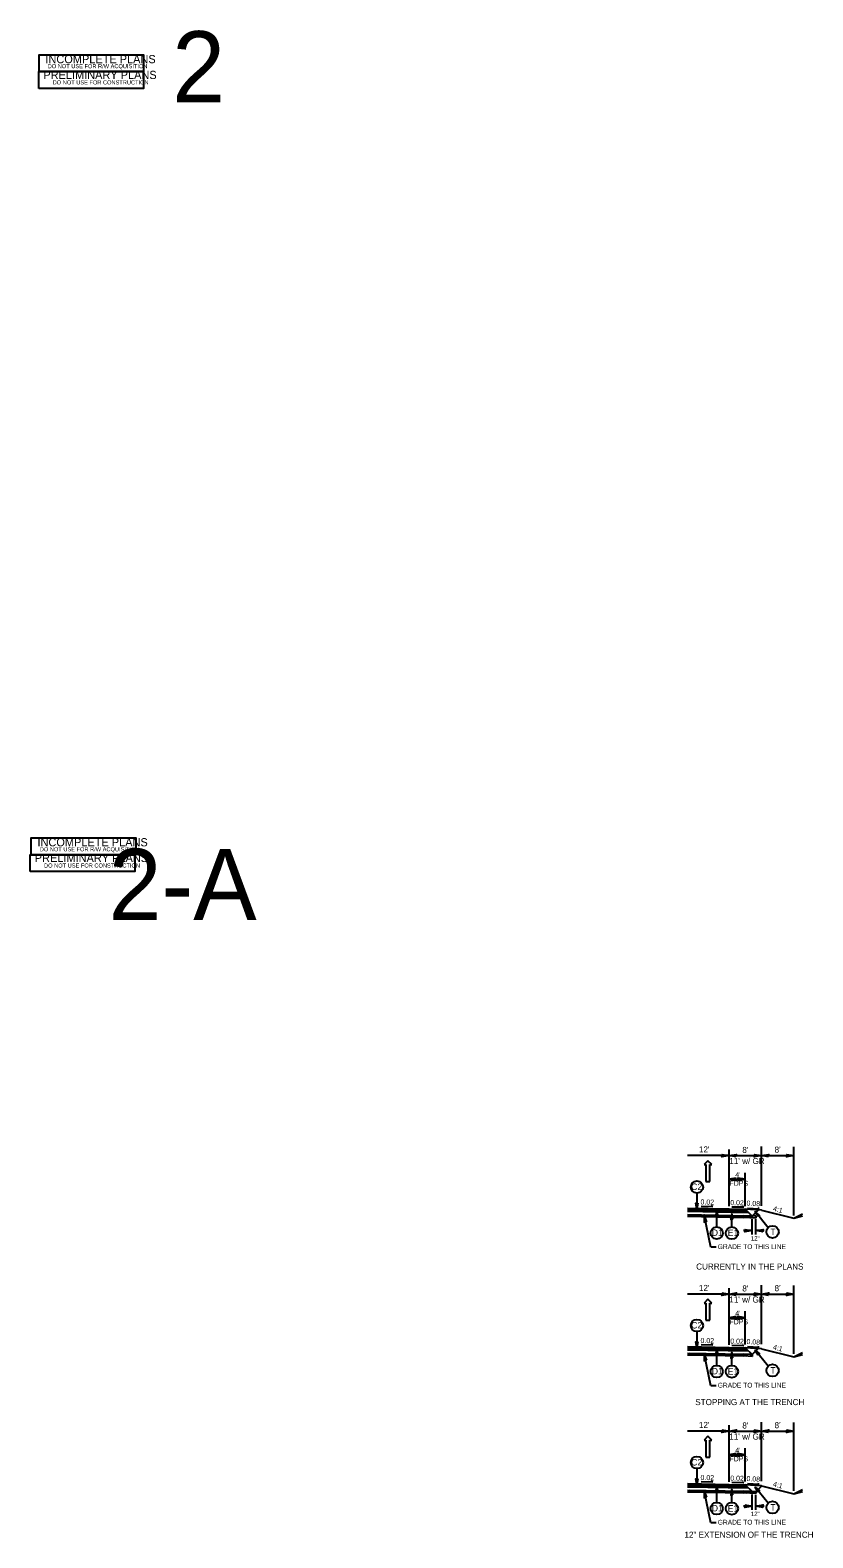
# Model space of a CAD drawing. Extents: x 573813 to 575363, y -54752 to -53123.
# Drawn here: x 575011.9 to 575232, y -53556.2 to -53132.5 of the extents above; entities that cross this region are included whole.
import ezdxf

# ---------------------------------------------------------------- set-up
doc = ezdxf.new("R2010")
doc.units = 0
for name, color, linetype in [('Old_Level_1', 7, 'Continuous'), ('Old_Level_11', 7, 'Continuous'), ('Old_Level_2', 7, 'Continuous'), ('Old_Level_3', 7, 'Continuous'), ('Prop Lane Arrow CELL', 7, 'Continuous'), ('Prop Pavement Schedule Description CELL', 7, 'Continuous'), ('Sheet Data Field CELL', 7, 'Continuous'), ('Sheet Sticker Incomplete CELL', 7, 'Continuous'), ('Sheet Sticker Preliminary CELL', 7, 'Continuous'), ('Typical ID Circle CELL', 7, 'Continuous'), ('Typical Terminator CELL', 7, 'Continuous'), ('Typical Text ID Circle CELL', 7, 'Continuous')]:
    doc.layers.add(name, color=color, linetype=linetype)

msp = doc.modelspace()

# ---------------------------------------------------------------- linework, layer by layer
at = {"layer": 'Old_Level_1'}
for p, q in [((575196.75, -53463.55), (575208.4, -53463.79)), ((575196.75, -53463.99), (575213.4, -53464.34)), ((575196.75, -53464.43), (575213.85, -53464.79)), ((575196.75, -53465.37), (575212.53, -53465.69)), ((575197.03, -53465.37), (575197.54, -53465.88)), ((575198.48, -53465.4), (575198.99, -53465.91)), ((575199.92, -53465.43), (575200.43, -53465.94)), ((575200.54, -53463.01), (575203.8, -53463.08)), ((575201.37, -53465.46), (575201.88, -53465.97)), ((575202.81, -53465.49), (575203.32, -53466)), ((575203.8, -53463.08), (575203.42, -53462.89)), ((575208.4, -53463.79), (575212.95, -53463.88)), ((575212.95, -53463.88), (575214.88, -53465.82)), ((575217.5, -53464.15), (575212.95, -53463.88)), ((575216.6, -53464.1), (575214.88, -53465.82)), ((575217.5, -53464.15), (575226.59, -53466.42)), ((575226.59, -53466.42), (575229.08, -53465.18)), ((575196.75, -53465.87), (575212.52, -53466.19)), ((575204.26, -53465.52), (575204.77, -53466.03)), ((575205.7, -53465.55), (575206.21, -53466.06)), ((575207.14, -53465.58), (575207.65, -53466.09)), ((575208.59, -53465.61), (575209.1, -53466.12)), ((575210.03, -53465.64), (575210.54, -53466.15)), ((575211.48, -53465.67), (575211.99, -53466.18)), ((575215.96, -53466.37), (575212.52, -53466.19)), ((575215.96, -53465.87), (575212.53, -53465.69)), ((575212.93, -53465.71), (575213.46, -53466.24)), ((575214.43, -53465.79), (575214.95, -53466.32)), ((575215.92, -53465.87), (575215.96, -53465.91)), ((575215.96, -53465.87), (575215.96, -53466.37)), ((575226.59, -53466.42), (575229.08, -53465.76)), ((575196.75, -53502.48), (575208.4, -53502.72)), ((575196.75, -53502.92), (575213.4, -53503.27)), ((575196.75, -53503.36), (575213.85, -53503.72)), ((575200.54, -53501.94), (575203.8, -53502.01)), ((575203.8, -53502.01), (575203.42, -53501.82)), ((575208.4, -53502.72), (575212.95, -53502.81)), ((575212.95, -53502.81), (575214.88, -53504.75)), ((575217.5, -53503.08), (575212.95, -53502.81)), ((575216.57, -53503.06), (575214.88, -53504.75)), ((575217.5, -53503.08), (575226.59, -53505.35)), ((575196.75, -53504.3), (575212.53, -53504.63)), ((575196.75, -53504.8), (575212.52, -53505.12)), ((575197.03, -53504.3), (575197.54, -53504.81)), ((575198.48, -53504.33), (575198.99, -53504.84)), ((575199.92, -53504.36), (575200.43, -53504.87)), ((575201.37, -53504.39), (575201.88, -53504.9)), ((575202.81, -53504.42), (575203.32, -53504.93)), ((575204.26, -53504.45), (575204.77, -53504.96)), ((575205.7, -53504.48), (575206.21, -53504.99)), ((575207.14, -53504.51), (575207.65, -53505.02)), ((575208.59, -53504.54), (575209.1, -53505.05)), ((575210.03, -53504.57), (575210.54, -53505.08)), ((575211.48, -53504.6), (575211.99, -53505.11)), ((575214.88, -53505.25), (575212.52, -53505.12)), ((575214.88, -53504.75), (575212.53, -53504.63)), ((575212.93, -53504.65), (575213.46, -53505.17)), ((575214.43, -53504.72), (575214.88, -53505.18)), ((575214.88, -53504.75), (575214.88, -53505.25)), ((575226.59, -53505.35), (575229.08, -53504.11)), ((575226.59, -53505.35), (575229.08, -53504.69)), ((575196.75, -53540.99), (575208.4, -53541.23)), ((575196.75, -53541.44), (575213.4, -53541.78)), ((575200.54, -53540.45), (575203.8, -53540.52)), ((575203.8, -53540.52), (575203.42, -53540.33)), ((575208.4, -53541.23), (575212.95, -53541.33)), ((575212.95, -53541.33), (575214.88, -53543.26)), ((575217.5, -53541.59), (575212.95, -53541.33)), ((575217.64, -53541.63), (575215.96, -53543.32)), ((575217.5, -53541.59), (575226.59, -53543.87)), ((575196.75, -53541.88), (575213.85, -53542.23)), ((575196.75, -53542.81), (575212.53, -53543.14)), ((575196.75, -53543.31), (575212.52, -53543.64)), ((575197.03, -53542.82), (575197.54, -53543.33)), ((575198.48, -53542.85), (575198.99, -53543.36)), ((575199.92, -53542.88), (575200.43, -53543.39)), ((575201.37, -53542.91), (575201.88, -53543.42)), ((575202.81, -53542.94), (575203.32, -53543.45)), ((575204.26, -53542.97), (575204.77, -53543.48)), ((575205.7, -53543), (575206.21, -53543.51)), ((575207.14, -53543.03), (575207.65, -53543.54)), ((575208.59, -53543.06), (575209.1, -53543.57)), ((575210.03, -53543.09), (575210.54, -53543.6)), ((575211.48, -53543.12), (575211.99, -53543.63)), ((575215.96, -53543.82), (575212.52, -53543.64)), ((575215.96, -53543.32), (575212.53, -53543.14)), ((575212.93, -53543.16), (575213.46, -53543.69)), ((575214.43, -53543.24), (575214.95, -53543.76)), ((575215.92, -53543.31), (575215.96, -53543.36)), ((575215.96, -53543.32), (575215.96, -53543.82)), ((575226.59, -53543.87), (575229.08, -53542.62)), ((575226.59, -53543.87), (575229.08, -53543.2))]:
    msp.add_line(p, q, dxfattribs=at)
at = {"layer": 'Old_Level_11'}
for p, q in [((575208.4, -53463.06), (575208.4, -53447.09)), ((575217.5, -53462.9), (575217.5, -53446.29)), ((575226.61, -53465.62), (575226.61, -53446.38)), ((575208.4, -53448.82), (575196.75, -53448.82)), ((575208.4, -53448.82), (575217.5, -53448.82)), ((575217.5, -53448.82), (575226.59, -53448.82)), ((575208.4, -53455.46), (575212.95, -53455.47)), ((575212.95, -53463), (575212.95, -53453.62)), ((575203.29, -53474.58), (575201.38, -53465.46)), ((575214.87, -53470.97), (575214.87, -53466.66)), ((575215.95, -53470.97), (575215.95, -53466.68)), ((575214.87, -53469.89), (575212.44, -53469.9)), ((575218.3, -53469.89), (575215.95, -53469.89)), ((575204.8, -53474.58), (575203.29, -53474.58)), ((575208.4, -53501.99), (575208.4, -53486.02)), ((575217.5, -53501.83), (575217.5, -53485.23)), ((575226.61, -53504.55), (575226.61, -53485.31)), ((575208.4, -53487.75), (575196.75, -53487.75)), ((575208.4, -53487.75), (575217.5, -53487.75)), ((575217.5, -53487.75), (575226.59, -53487.75)), ((575208.4, -53494.39), (575212.95, -53494.4)), ((575212.95, -53501.93), (575212.95, -53492.55)), ((575203.29, -53513.51), (575201.38, -53504.39)), ((575204.8, -53513.51), (575203.29, -53513.51)), ((575208.4, -53540.5), (575208.4, -53524.53)), ((575217.5, -53540.34), (575217.5, -53523.74)), ((575226.61, -53543.06), (575226.61, -53523.82)), ((575208.4, -53526.27), (575196.75, -53526.27)), ((575208.4, -53526.27), (575217.5, -53526.27)), ((575217.5, -53526.27), (575226.59, -53526.27)), ((575208.4, -53532.91), (575212.95, -53532.91)), ((575212.95, -53540.44), (575212.95, -53531.06)), ((575203.29, -53552.02), (575201.38, -53542.91)), ((575214.87, -53548.42), (575214.87, -53544.1)), ((575215.95, -53548.42), (575215.95, -53544.13)), ((575214.87, -53547.34), (575212.44, -53547.34)), ((575218.3, -53547.33), (575215.95, -53547.34)), ((575204.8, -53552.02), (575203.29, -53552.02))]:
    msp.add_line(p, q, dxfattribs=at)
for points in [[(575206.35, -53448.47), (575208.4, -53448.82), (575206.34, -53449.19), (575206.6, -53448.82)], [(575210.45, -53449.17), (575208.4, -53448.82), (575210.46, -53448.46), (575210.2, -53448.82)], [(575215.45, -53448.47), (575217.5, -53448.82), (575215.44, -53449.19), (575215.7, -53448.82)], [(575219.54, -53449.17), (575217.5, -53448.82), (575219.55, -53448.46), (575219.29, -53448.82)], [(575224.55, -53448.47), (575226.59, -53448.82), (575224.54, -53449.19), (575224.8, -53448.82)], [(575210.45, -53455.11), (575208.4, -53455.46), (575210.46, -53455.82), (575210.2, -53455.46)], [(575210.9, -53455.82), (575212.95, -53455.47), (575210.89, -53455.1), (575211.15, -53455.47)], [(575202.15, -53467.39), (575201.38, -53465.46), (575201.45, -53467.55), (575201.75, -53467.22)], [(575212.82, -53469.54), (575214.87, -53469.89), (575212.81, -53470.26), (575213.07, -53469.89)], [(575217.99, -53470.24), (575215.95, -53469.89), (575218, -53469.53), (575217.74, -53469.89)], [(575206.35, -53487.4), (575208.4, -53487.75), (575206.34, -53488.12), (575206.6, -53487.75)], [(575210.45, -53488.11), (575208.4, -53487.75), (575210.46, -53487.39), (575210.2, -53487.75)], [(575215.45, -53487.4), (575217.5, -53487.75), (575215.44, -53488.12), (575215.7, -53487.75)], [(575219.54, -53488.11), (575217.5, -53487.75), (575219.55, -53487.39), (575219.29, -53487.75)], [(575224.55, -53487.4), (575226.59, -53487.75), (575224.54, -53488.12), (575224.8, -53487.75)], [(575210.45, -53494.04), (575208.4, -53494.39), (575210.46, -53494.76), (575210.2, -53494.39)], [(575210.9, -53494.75), (575212.95, -53494.4), (575210.89, -53494.03), (575211.15, -53494.4)], [(575202.15, -53506.32), (575201.38, -53504.39), (575201.45, -53506.48), (575201.75, -53506.15)], [(575206.35, -53525.91), (575208.4, -53526.27), (575206.34, -53526.63), (575206.6, -53526.27)], [(575210.45, -53526.62), (575208.4, -53526.27), (575210.46, -53525.9), (575210.2, -53526.27)], [(575215.45, -53525.91), (575217.5, -53526.27), (575215.44, -53526.63), (575215.7, -53526.27)], [(575219.54, -53526.62), (575217.5, -53526.27), (575219.55, -53525.9), (575219.29, -53526.27)], [(575224.55, -53525.91), (575226.59, -53526.27), (575224.54, -53526.63), (575224.8, -53526.27)], [(575210.45, -53532.55), (575208.4, -53532.91), (575210.46, -53533.27), (575210.2, -53532.91)], [(575210.9, -53533.26), (575212.95, -53532.91), (575210.89, -53532.55), (575211.15, -53532.91)], [(575202.15, -53544.84), (575201.38, -53542.91), (575201.45, -53545), (575201.75, -53544.66)], [(575212.82, -53546.98), (575214.87, -53547.34), (575212.81, -53547.7), (575213.07, -53547.34)], [(575217.99, -53547.69), (575215.95, -53547.34), (575218, -53546.97), (575217.74, -53547.34)]]:
    msp.add_lwpolyline(points, close=True, dxfattribs=at)
at = {"layer": 'Old_Level_2'}
for p, q in [((575212.58, -53463.34), (575209.14, -53463.27)), ((575212.58, -53463.34), (575212.15, -53463.08)), ((575213.61, -53463.57), (575216.86, -53463.76)), ((575216.86, -53463.76), (575216.48, -53463.58)), ((575212.58, -53502.27), (575209.14, -53502.2)), ((575212.58, -53502.27), (575212.15, -53502.01)), ((575213.61, -53502.5), (575216.86, -53502.69)), ((575216.86, -53502.69), (575216.48, -53502.51)), ((575212.58, -53540.78), (575209.14, -53540.72)), ((575212.58, -53540.78), (575212.15, -53540.52)), ((575213.61, -53541.01), (575216.86, -53541.2)), ((575216.86, -53541.2), (575216.48, -53541.02))]:
    msp.add_line(p, q, dxfattribs=at)
at = {"layer": 'Prop Lane Arrow CELL'}
for p, q in [((575202.46, -53450.25), (575201.37, -53451.33)), ((575201.37, -53451.33), (575201.88, -53451.33)), ((575201.88, -53451.33), (575201.88, -53456.1)), ((575203.52, -53451.33), (575202.46, -53450.25)), ((575203, -53456.1), (575203, -53451.33)), ((575203, -53451.33), (575203.52, -53451.33)), ((575201.88, -53456.1), (575203, -53456.1)), ((575202.46, -53489.18), (575201.37, -53490.26)), ((575201.37, -53490.26), (575201.88, -53490.26)), ((575201.88, -53490.26), (575201.88, -53495.03)), ((575203.52, -53490.26), (575202.46, -53489.18)), ((575203, -53495.03), (575203, -53490.26)), ((575203, -53490.26), (575203.52, -53490.26)), ((575201.88, -53495.03), (575203, -53495.03)), ((575202.46, -53527.7), (575201.37, -53528.77)), ((575201.37, -53528.77), (575201.88, -53528.77)), ((575201.88, -53528.77), (575201.88, -53533.55)), ((575203.52, -53528.77), (575202.46, -53527.7)), ((575203, -53533.55), (575203, -53528.77)), ((575203, -53528.77), (575203.52, -53528.77)), ((575201.88, -53533.55), (575203, -53533.55))]:
    msp.add_line(p, q, dxfattribs=at)
at = {"layer": 'Sheet Sticker Incomplete CELL'}
for points in [[(575014.4, -53144.11), (575014.4, -53139.4), (575043.81, -53139.4), (575043.81, -53144.11)], [(575012.17, -53364.22), (575012.17, -53359.52), (575041.58, -53359.52), (575041.58, -53364.22)]]:
    msp.add_lwpolyline(points, close=True, dxfattribs=at)
at = {"layer": 'Sheet Sticker Preliminary CELL'}
for points in [[(575014.31, -53148.81), (575014.31, -53144.11), (575043.73, -53144.11), (575043.73, -53148.81)], [(575011.9, -53368.93), (575011.9, -53364.22), (575041.32, -53364.22), (575041.32, -53368.93)]]:
    msp.add_lwpolyline(points, close=True, dxfattribs=at)
at = {"layer": 'Typical ID Circle CELL'}
for p, q in [((575199.39, -53459.34), (575199.39, -53463.78)), ((575204.93, -53468.84), (575204.93, -53464.4)), ((575209.21, -53468.87), (575209.21, -53465.2)), ((575219.39, -53469.08), (575215.78, -53464.55)), ((575199.39, -53498.27), (575199.39, -53502.71)), ((575204.93, -53507.77), (575204.93, -53503.33)), ((575219.39, -53508.01), (575215.78, -53503.48)), ((575209.21, -53507.8), (575209.21, -53504.13)), ((575199.39, -53536.79), (575199.39, -53541.23)), ((575204.93, -53546.28), (575204.93, -53541.84)), ((575209.21, -53546.31), (575209.21, -53542.64)), ((575219.39, -53546.52), (575215.78, -53541.99))]:
    msp.add_line(p, q, dxfattribs=at)
for centre in [(575199.39, -53457.63), (575204.93, -53470.56), (575209.21, -53470.58), (575220.65, -53470.25), (575199.39, -53496.56), (575204.93, -53509.49), (575209.21, -53509.51), (575220.65, -53509.18), (575199.39, -53535.07), (575220.65, -53547.69), (575204.93, -53548), (575209.21, -53548.03)]:
    msp.add_circle(centre, 1.72, dxfattribs=at)
at = {"layer": 'Typical Terminator CELL'}
for points in [[(575199.67, -53462.19), (575199.39, -53463.78), (575199.11, -53462.18), (575199.39, -53462.39)], [(575204.66, -53465.99), (575204.93, -53464.4), (575205.21, -53466), (575204.93, -53465.8)], [(575209.48, -53466.79), (575209.21, -53465.2), (575208.92, -53466.8), (575209.21, -53466.6)], [(575216.55, -53465.96), (575215.78, -53464.55), (575216.99, -53465.62), (575216.65, -53465.64)], [(575199.67, -53501.12), (575199.39, -53502.71), (575199.11, -53501.11), (575199.39, -53501.32)], [(575204.66, -53504.92), (575204.93, -53503.33), (575205.21, -53504.93), (575204.93, -53504.73)], [(575216.55, -53504.89), (575215.78, -53503.48), (575216.99, -53504.55), (575216.65, -53504.57)], [(575209.48, -53505.72), (575209.21, -53504.13), (575208.92, -53505.73), (575209.21, -53505.53)], [(575199.67, -53539.64), (575199.39, -53541.23), (575199.11, -53539.63), (575199.39, -53539.83)], [(575204.66, -53543.43), (575204.93, -53541.84), (575205.21, -53543.44), (575204.93, -53543.24)], [(575209.48, -53544.23), (575209.21, -53542.64), (575208.92, -53544.24), (575209.21, -53544.04)], [(575216.55, -53543.41), (575215.78, -53541.99), (575216.99, -53543.07), (575216.65, -53543.09)]]:
    msp.add_lwpolyline(points, close=True, dxfattribs=at)

# ---------------------------------------------------------------- texts
at = {"layer": 'Old_Level_1'}
for s, rotation, p in [('FDPS', 359.9999, (575208.53, -53457.29)), ('0.02', 358.8084, (575200.37, -53462.53)), ('0.08', 356.5794, (575213.28, -53462.83)), ('4:1', 345.3432, (575220.64, -53464.3)), ('FDPS', 359.9999, (575208.53, -53496.22)), ('0.02', 358.8084, (575200.37, -53501.47)), ('0.08', 356.5794, (575213.28, -53501.76)), ('4:1', 345.3432, (575220.64, -53503.23)), ('FDPS', 359.9999, (575208.53, -53534.74)), ('0.02', 358.8084, (575200.37, -53539.98)), ('0.08', 356.5794, (575213.28, -53540.27)), ('4:1', 345.3432, (575220.64, -53541.74))]:
    msp.add_text(s, height=1.421, rotation=rotation, dxfattribs=at).set_placement(p)
at = {"layer": 'Old_Level_11'}
for s, height, p in [("12'", 1.705, (575199.94, -53447.92)), ("8'", 1.705, (575221.2, -53447.99)), ('GRADE TO THIS LINE', 1.3502, (575205.23, -53475.08)), ('CURRENTLY IN THE PLANS', 1.7055, (575199.17, -53480.84)), ("12'", 1.705, (575199.94, -53486.85)), ("8'", 1.705, (575221.2, -53486.92)), ('GRADE TO THIS LINE', 1.3502, (575205.23, -53514.01)), ('STOPPING AT THE TRENCH', 1.7055, (575198.9, -53518.94)), ("12'", 1.705, (575199.94, -53525.36)), ("8'", 1.705, (575221.2, -53525.43)), ('12" EXTENSION OF THE TRENCH', 1.7055, (575195.86, -53556.22)), ('GRADE TO THIS LINE', 1.3502, (575205.23, -53552.53))]:
    msp.add_text(s, height=height, rotation=360, dxfattribs=at).set_placement(p)
at = {"layer": 'Old_Level_3'}
for s, height, rotation, p in [("8'", 1.705, 359.8329, (575212.13, -53448.06)), ("11' w/ GR", 1.705, 359.8329, (575208.48, -53451.16)), ("4'", 1.421, 359.8329, (575210.15, -53454.89)), ('0.02', 1.421, 358.8543, (575208.73, -53462.71)), ("8'", 1.705, 359.8329, (575212.13, -53486.99)), ("11' w/ GR", 1.705, 359.8329, (575208.48, -53490.09)), ("4'", 1.421, 359.8329, (575210.15, -53493.82)), ('0.02', 1.421, 358.8543, (575208.73, -53501.64)), ("8'", 1.705, 359.8329, (575212.13, -53525.51)), ("11' w/ GR", 1.705, 359.8329, (575208.48, -53528.61)), ("4'", 1.421, 359.8329, (575210.15, -53532.33)), ('0.02', 1.421, 358.8543, (575208.73, -53540.16))]:
    msp.add_text(s, height=height, rotation=rotation, dxfattribs=at).set_placement(p)
at = {"layer": 'Prop Pavement Schedule Description CELL'}
for s, p in [('C2', (575197.75, -53458.47)), ('D1', (575203.55, -53471.37)), ('E1', (575208.04, -53471.42)), ('C2', (575197.75, -53497.4)), ('D1', (575203.55, -53510.3)), ('E1', (575208.04, -53510.35)), ('C2', (575197.75, -53535.91)), ('D1', (575203.55, -53548.82)), ('E1', (575208.04, -53548.87))]:
    msp.add_text(s, height=1.819, rotation=360, dxfattribs=at).set_placement(p)
for p in [(575220.02, -53471.16), (575220.02, -53510.09), (575220.02, -53548.6)]:
    msp.add_text('T', height=1.82, dxfattribs=at).set_placement(p)
at = {"layer": 'Sheet Data Field CELL'}
for s, p in [('2', (575051.84, -53152.75)), ('2-A', (575033.97, -53382.58))]:
    msp.add_text(s, height=20, dxfattribs=at).set_placement(p)
at = {"layer": 'Sheet Sticker Incomplete CELL'}
for s, height, p in [('INCOMPLETE PLANS', 2.3052, (575016.19, -53141.76)), ('DO NOT USE FOR R/W ACQUISITION', 1.1526, (575016.84, -53143.16)), ('INCOMPLETE PLANS', 2.3052, (575013.96, -53361.88)), ('DO NOT USE FOR R/W ACQUISITION', 1.1526, (575014.61, -53363.27))]:
    msp.add_text(s, height=height, dxfattribs=at).set_placement(p)
at = {"layer": 'Sheet Sticker Preliminary CELL'}
for s, height, p in [('PRELIMINARY PLANS', 2.3052, (575015.61, -53146.18)), ('DO NOT USE FOR CONSTRUCTION', 1.1526, (575018.24, -53147.72)), ('PRELIMINARY PLANS', 2.3052, (575013.2, -53366.29)), ('DO NOT USE FOR CONSTRUCTION', 1.1526, (575015.82, -53367.84))]:
    msp.add_text(s, height=height, dxfattribs=at).set_placement(p)
at = {"layer": 'Typical Text ID Circle CELL'}
for p in [(575214.52, -53472.68), (575214.52, -53550.13)]:
    msp.add_text('12"', height=1.23, dxfattribs=at).set_placement(p)

doc.saveas('drawing.dxf')
